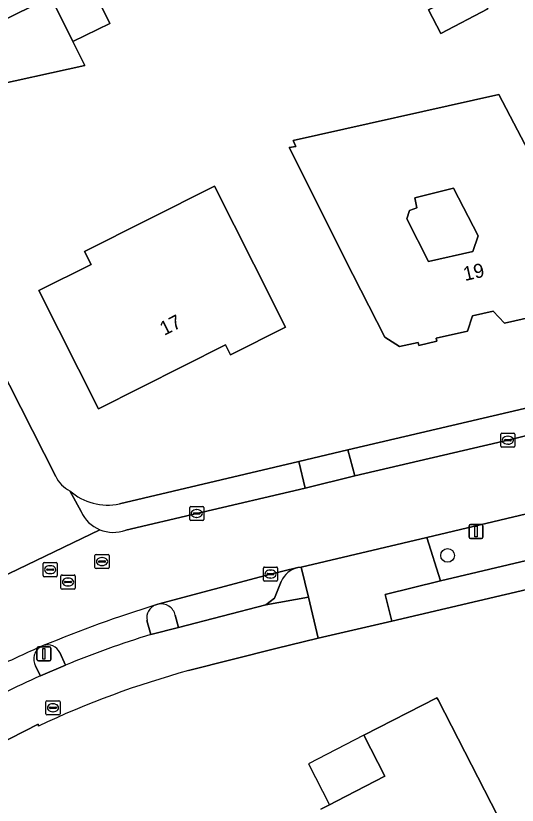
# Model space of a CAD drawing. Extents: x 162722 to 165104, y 384719 to 386284.
# Drawn here: x 163906.4 to 163942.1, y 384936 to 384992.1 of the extents above; entities that cross this region are included whole.
import ezdxf

# ---------------------------------------------------------------- set-up
doc = ezdxf.new("R2010")
doc.units = 0
for name, color, linetype in [('IMGEO_Boom', 7, 'Continuous'), ('IMGEO_Brandkraan', 7, 'Continuous'), ('IMGEO_Erf', 7, 'Continuous'), ('IMGEO_Groenvoorziening', 7, 'Continuous'), ('IMGEO_Kolk', 7, 'Continuous'), ('IMGEO_Lichtmast', 7, 'Continuous'), ('IMGEO_Pand', 7, 'Continuous'), ('IMGEO_Pand_nummerreeks', 7, 'Continuous'), ('IMGEO_Pand_overbouw', 7, 'Continuous'), ('IMGEO_Parkeervlak_open', 7, 'Continuous'), ('IMGEO_Rijbaan_lokaal_open', 7, 'Continuous'), ('IMGEO_Rioolput', 7, 'Continuous'), ('IMGEO_Voetpad_open', 7, 'Continuous')]:
    doc.layers.add(name, color=color, linetype=linetype)

msp = doc.modelspace()

# ---------------------------------------------------------------- linework, layer by layer
at = {"layer": 'IMGEO_Boom'}
msp.add_circle((163937.119, 384953.735), 0.489, dxfattribs=at)
at = {"layer": 'IMGEO_Brandkraan'}
for p, q in [((163908.59, 384942.495), (163908.59, 384943.347)), ((163908.665, 384943.421), (163909.517, 384943.421)), ((163908.849, 384942.915), (163908.849, 384942.927)), ((163908.892, 384942.964), (163909.29, 384942.964)), ((163909.078, 384943.201), (163909.103, 384943.201)), ((163909.333, 384942.927), (163909.333, 384942.915)), ((163909.591, 384943.347), (163909.591, 384942.495)), ((163909.517, 384942.421), (163908.665, 384942.421)), ((163909.287, 384942.878), (163908.889, 384942.878)), ((163909.101, 384942.641), (163909.076, 384942.641))]:
    msp.add_line(p, q, dxfattribs=at)
for points in [[(163908.59, 384942.495), (163908.59, 384943.347)], [(163908.665, 384943.421), (163909.517, 384943.421)], [(163909.591, 384943.347), (163909.591, 384942.495)], [(163909.517, 384942.421), (163908.665, 384942.421)]]:
    msp.add_lwpolyline(points, dxfattribs=at)
for centre, radius, start, end in [((163908.667, 384943.345), 0.0765, 91.552, 178.448), ((163908.667, 384943.345), 0.0765, 91.552, 178.448), ((163908.889, 384942.924), 0.0403, 85.8775, 175.7526), ((163908.886, 384942.914), 0.0366, 178.938, 274.7102), ((163909.29, 384942.921), 0.043, 264.8664, 352.4533), ((163909.294, 384942.926), 0.0386, 1.7309, 96.639), ((163909.515, 384943.345), 0.0765, 1.552, 88.448), ((163909.515, 384943.345), 0.0765, 1.552, 88.448), ((163908.667, 384942.497), 0.0765, 181.552, 268.448), ((163908.667, 384942.497), 0.0765, 181.552, 268.448), ((163909.515, 384942.497), 0.0765, 271.552, 358.448), ((163909.515, 384942.497), 0.0765, 271.552, 358.448)]:
    msp.add_arc(centre, radius, start, end, dxfattribs=at)
for centre, major_axis, ratio, start_param, end_param in [((163909.077, 384942.921), (-0.387, 0.002), 0.722429, 4.712389, 7.853982), ((163909.102, 384942.921), (-0.39, 0.002), 0.717154, 1.570796, 4.712389)]:
    msp.add_ellipse(centre, major_axis=major_axis, ratio=ratio, start_param=start_param, end_param=end_param, dxfattribs=at)
at = {"layer": 'IMGEO_Erf'}
for points in [[(163882.032, 385013.018), (163888.642, 385000), (163909.281, 384959.35)], [(163913.816, 384957.404), (163926.539, 384960.407), (163930.036, 384961.223), (163943.693, 384964.44), (163948.458, 384965.545), (163956.397, 384967.448), (163961.373, 384968.617), (163971.306, 384970.962)], [(163975.92, 384959.258), (163968.134, 384957.317), (163963.115, 384956.107), (163933.164, 384949.08), (163927.927, 384947.854), (163924.926, 384947.138), (163918.721, 384945.558)], [(163928.112, 384935.718), (163928.727, 384936.034), (163929.219, 384936.287), (163932.661, 384938.054), (163931.165, 384940.968), (163936.357, 384943.634), (163936.439, 384943.474), (163941.619, 384933.387)], [(163908.065, 384941.624), (163908.032, 384941.753), (163901.088, 384938.216)]]:
    msp.add_lwpolyline(points, dxfattribs=at)
for points in [[(163911.349, 384988.529), (163904.023, 384986.91), (163902.431, 384990.1), (163902.388, 384990.186), (163908.918, 384993.403), (163909.148, 384992.941), (163911.782, 384994.239), (163913.125, 384991.512), (163910.505, 384990.221)], [(163935.761, 384992.482), (163939.091, 384994.231), (163939.975, 384992.549), (163936.645, 384990.8)], [(163940.76, 384986.466), (163945.807, 384976.829), (163948.127, 384972.399), (163947.687, 384972.29), (163947.865, 384971.742), (163941.151, 384970.237), (163940.349, 384971.083), (163938.885, 384970.754), (163938.527, 384969.649), (163936.314, 384969.153), (163936.363, 384968.939), (163935.075, 384968.65), (163935.026, 384968.863), (163933.698, 384968.566), (163932.657, 384969.226), (163930.383, 384973.68), (163925.858, 384982.688), (163926.334, 384982.782), (163926.145, 384983.19)], [(163915.805, 384977.558), (163920.563, 384979.952), (163923.347, 384974.42), (163925.595, 384969.953), (163921.691, 384967.989), (163921.339, 384968.688), (163912.311, 384964.145), (163908.088, 384972.536), (163911.796, 384974.401), (163911.338, 384975.31)], [(163934.778, 384979.126), (163934.942, 384978.416), (163934.419, 384978.233), (163934.211, 384977.636), (163935.758, 384974.607), (163938.9, 384975.313), (163939.291, 384976.438), (163937.528, 384979.804)]]:
    msp.add_lwpolyline(points, close=True, dxfattribs=at)
for centre, radius, start, end in [((163911.238, 384960.278), 2.166, 205.3701, 244.008), ((163912.954, 384961.299), 3.989, 228.0763, 282.4718), ((163936.044, 384882.237), 65.648, 105.30008, 115.22637)]:
    msp.add_arc(centre, radius, start, end, dxfattribs=at)
at = {"layer": 'IMGEO_Groenvoorziening'}
msp.add_lwpolyline([(163936.605, 384951.924), (163962.352, 384958.013), (163960.784, 384960.984), (163958.798, 384960.498), (163942.724, 384956.689), (163935.642, 384955.001)], close=True, dxfattribs=at)
at = {"layer": 'IMGEO_Kolk'}
for p, q in [((163940.895, 384961.491), (163940.895, 384962.343)), ((163940.97, 384962.417), (163941.822, 384962.417)), ((163941.197, 384961.96), (163941.595, 384961.96)), ((163941.383, 384962.197), (163941.408, 384962.197)), ((163941.896, 384962.343), (163941.896, 384961.491)), ((163941.822, 384961.417), (163940.97, 384961.417)), ((163941.154, 384961.911), (163941.154, 384961.923)), ((163941.592, 384961.874), (163941.194, 384961.874)), ((163941.406, 384961.637), (163941.381, 384961.637)), ((163941.638, 384961.923), (163941.638, 384961.911)), ((163918.799, 384956.286), (163918.799, 384957.138)), ((163918.874, 384957.212), (163919.726, 384957.212)), ((163919.287, 384956.992), (163919.312, 384956.992)), ((163919.8, 384957.138), (163919.8, 384956.286)), ((163919.058, 384956.706), (163919.058, 384956.718)), ((163919.496, 384956.669), (163919.098, 384956.669)), ((163919.101, 384956.755), (163919.499, 384956.755)), ((163919.31, 384956.432), (163919.285, 384956.432)), ((163919.542, 384956.718), (163919.542, 384956.706)), ((163919.726, 384956.212), (163918.874, 384956.212)), ((163924.039, 384951.987), (163924.039, 384952.839)), ((163924.114, 384952.913), (163924.966, 384952.913)), ((163924.341, 384952.456), (163924.739, 384952.456)), ((163924.527, 384952.693), (163924.552, 384952.693)), ((163925.04, 384952.839), (163925.04, 384951.987)), ((163924.966, 384951.913), (163924.114, 384951.913)), ((163924.298, 384952.407), (163924.298, 384952.419)), ((163924.736, 384952.37), (163924.338, 384952.37)), ((163924.55, 384952.133), (163924.525, 384952.133)), ((163924.782, 384952.419), (163924.782, 384952.407))]:
    msp.add_line(p, q, dxfattribs=at)
for points in [[(163940.895, 384961.491), (163940.895, 384962.343)], [(163940.97, 384962.417), (163941.822, 384962.417)], [(163941.896, 384962.343), (163941.896, 384961.491)], [(163941.822, 384961.417), (163940.97, 384961.417)], [(163918.799, 384956.286), (163918.799, 384957.138)], [(163918.874, 384957.212), (163919.726, 384957.212)], [(163919.8, 384957.138), (163919.8, 384956.286)], [(163919.726, 384956.212), (163918.874, 384956.212)], [(163924.039, 384951.987), (163924.039, 384952.839)], [(163924.114, 384952.913), (163924.966, 384952.913)], [(163925.04, 384952.839), (163925.04, 384951.987)], [(163924.966, 384951.913), (163924.114, 384951.913)]]:
    msp.add_lwpolyline(points, dxfattribs=at)
for centre, radius, start, end in [((163940.972, 384962.341), 0.0765, 91.552, 178.448), ((163940.972, 384962.341), 0.0765, 91.552, 178.448), ((163941.194, 384961.92), 0.0403, 85.8775, 175.7526), ((163941.599, 384961.922), 0.0386, 1.7309, 96.639), ((163941.82, 384962.341), 0.0765, 1.552, 88.448), ((163941.82, 384962.341), 0.0765, 1.552, 88.448), ((163940.972, 384961.493), 0.0765, 181.552, 268.448), ((163940.972, 384961.493), 0.0765, 181.552, 268.448), ((163941.191, 384961.91), 0.0366, 178.938, 274.7102), ((163941.595, 384961.917), 0.043, 264.8664, 352.4533), ((163941.82, 384961.493), 0.0765, 271.552, 358.448), ((163941.82, 384961.493), 0.0765, 271.552, 358.448), ((163918.876, 384957.136), 0.0765, 91.552, 178.448), ((163918.876, 384957.136), 0.0765, 91.552, 178.448), ((163919.724, 384957.136), 0.0765, 1.552, 88.448), ((163919.724, 384957.136), 0.0765, 1.552, 88.448), ((163919.098, 384956.715), 0.0403, 85.8775, 175.7526), ((163919.095, 384956.705), 0.0366, 178.938, 274.7102), ((163919.499, 384956.712), 0.043, 264.8664, 352.4533), ((163919.503, 384956.717), 0.0386, 1.7309, 96.639), ((163918.876, 384956.288), 0.0765, 181.552, 268.448), ((163918.876, 384956.288), 0.0765, 181.552, 268.448), ((163919.724, 384956.288), 0.0765, 271.552, 358.448), ((163919.724, 384956.288), 0.0765, 271.552, 358.448), ((163924.116, 384952.837), 0.0765, 91.552, 178.448), ((163924.116, 384952.837), 0.0765, 91.552, 178.448), ((163924.338, 384952.416), 0.0403, 85.8775, 175.7526), ((163924.743, 384952.418), 0.0386, 1.7309, 96.639), ((163924.964, 384952.837), 0.0765, 1.552, 88.448), ((163924.964, 384952.837), 0.0765, 1.552, 88.448), ((163924.116, 384951.989), 0.0765, 181.552, 268.448), ((163924.116, 384951.989), 0.0765, 181.552, 268.448), ((163924.335, 384952.406), 0.0366, 178.938, 274.7102), ((163924.739, 384952.413), 0.043, 264.8664, 352.4533), ((163924.964, 384951.989), 0.0765, 271.552, 358.448), ((163924.964, 384951.989), 0.0765, 271.552, 358.448)]:
    msp.add_arc(centre, radius, start, end, dxfattribs=at)
for centre, major_axis, ratio, start_param, end_param in [((163941.382, 384961.917), (-0.387, 0.002), 0.722429, 4.712389, 7.853982), ((163941.407, 384961.917), (-0.39, 0.002), 0.717154, 1.570796, 4.712389), ((163919.286, 384956.712), (-0.387, 0.002), 0.722429, 4.712389, 7.853982), ((163919.311, 384956.712), (-0.39, 0.002), 0.717154, 1.570796, 4.712389), ((163924.526, 384952.413), (-0.387, 0.002), 0.722429, 4.712389, 7.853982), ((163924.551, 384952.413), (-0.39, 0.002), 0.717154, 1.570796, 4.712389)]:
    msp.add_ellipse(centre, major_axis=major_axis, ratio=ratio, start_param=start_param, end_param=end_param, dxfattribs=at)
at = {"layer": 'IMGEO_Lichtmast'}
for p, q in [((163938.638, 384955.043), (163938.638, 384955.843)), ((163938.638, 384955.843), (163938.638, 384955.043)), ((163938.738, 384955.943), (163939.528, 384955.943)), ((163939.528, 384955.943), (163938.738, 384955.943)), ((163939.628, 384955.843), (163939.628, 384955.043)), ((163939.628, 384955.043), (163939.628, 384955.843)), ((163939.528, 384954.943), (163938.738, 384954.943)), ((163938.738, 384954.943), (163939.528, 384954.943)), ((163907.95, 384946.353), (163907.95, 384947.153)), ((163907.95, 384947.153), (163907.95, 384946.353)), ((163908.05, 384947.253), (163908.84, 384947.253)), ((163908.84, 384947.253), (163908.05, 384947.253)), ((163908.94, 384947.153), (163908.94, 384946.353)), ((163908.94, 384946.353), (163908.94, 384947.153)), ((163908.84, 384946.253), (163908.05, 384946.253)), ((163908.05, 384946.253), (163908.84, 384946.253))]:
    msp.add_line(p, q, dxfattribs=at)
for points in [[(163939.058, 384955.818), (163939.208, 384955.818), (163939.208, 384955.068), (163939.058, 384955.068), (163939.058, 384955.818)], [(163908.37, 384947.128), (163908.52, 384947.128), (163908.52, 384946.378), (163908.37, 384946.378), (163908.37, 384947.128)]]:
    msp.add_lwpolyline(points, dxfattribs=at)
for centre, start, end in [((163938.738, 384955.843), 90, 180), ((163938.738, 384955.843), 90, 180), ((163939.528, 384955.843), 0, 90), ((163939.528, 384955.843), 360, 90), ((163938.738, 384955.043), 180, 270), ((163938.738, 384955.043), 180, 270), ((163939.528, 384955.043), 270, 0), ((163939.528, 384955.043), 270, 0), ((163908.05, 384947.153), 90, 180), ((163908.05, 384947.153), 90, 180), ((163908.84, 384947.153), 0, 90), ((163908.84, 384947.153), 360, 90), ((163908.05, 384946.353), 180, 270), ((163908.05, 384946.353), 180, 270), ((163908.84, 384946.353), 270, 0), ((163908.84, 384946.353), 270, 0)]:
    msp.add_arc(centre, 0.1, start, end, dxfattribs=at)
at = {"layer": 'IMGEO_Pand'}
for points in [[(163911.782, 384994.239), (163909.148, 384992.941), (163910.505, 384990.221), (163913.125, 384991.512)], [(163935.761, 384992.482), (163936.645, 384990.8), (163939.975, 384992.549), (163939.091, 384994.231)], [(163910.505, 384990.221), (163909.148, 384992.941), (163908.918, 384993.403), (163902.388, 384990.186), (163902.431, 384990.1), (163904.023, 384986.91), (163911.349, 384988.529)], [(163945.807, 384976.829), (163940.76, 384986.466), (163926.145, 384983.19), (163926.334, 384982.782), (163925.858, 384982.688), (163930.383, 384973.68), (163932.657, 384969.226), (163933.698, 384968.566), (163935.026, 384968.863), (163935.075, 384968.65), (163936.363, 384968.939), (163936.314, 384969.153), (163938.527, 384969.649), (163938.885, 384970.754), (163940.349, 384971.083), (163941.151, 384970.237), (163947.865, 384971.742), (163947.687, 384972.29), (163948.127, 384972.399)], [(163911.338, 384975.31), (163911.796, 384974.401), (163908.088, 384972.536), (163912.311, 384964.145), (163921.339, 384968.688), (163921.691, 384967.989), (163925.595, 384969.953), (163923.347, 384974.42), (163920.563, 384979.952), (163915.805, 384977.558)], [(163934.778, 384979.126), (163937.528, 384979.804), (163939.291, 384976.438), (163938.9, 384975.313), (163935.758, 384974.607), (163934.211, 384977.636), (163934.419, 384978.233), (163934.942, 384978.416)]]:
    msp.add_lwpolyline(points, close=True, dxfattribs=at)
msp.add_lwpolyline([(163941.619, 384933.387), (163936.439, 384943.474), (163936.357, 384943.634), (163931.165, 384940.968), (163932.661, 384938.054), (163929.219, 384936.287), (163928.727, 384936.034), (163928.112, 384935.718)], dxfattribs=at)
at = {"layer": 'IMGEO_Pand_overbouw'}
msp.add_lwpolyline([(163931.165, 384940.968), (163927.231, 384938.948), (163928.727, 384936.034), (163929.219, 384936.287), (163932.661, 384938.054)], close=True, dxfattribs=at)
at = {"layer": 'IMGEO_Parkeervlak_open'}
msp.add_lwpolyline([(163930.539, 384959.379), (163941.396, 384961.917), (163944.127, 384962.571), (163943.693, 384964.44), (163930.036, 384961.223)], close=True, dxfattribs=at)
for points in [[(163927.004, 384958.519), (163926.539, 384960.407), (163913.816, 384957.404)], [(163910.289, 384958.331), (163911.083, 384956.847)], [(163914.255, 384955.535), (163919.3, 384956.712), (163927.004, 384958.519)], [(163926.475, 384952.875), (163924.54, 384952.413), (163916.547, 384950.264)], [(163917.774, 384949.488), (163917.994, 384948.624), (163924.21, 384950.228), (163924.811, 384950.701), (163925.3, 384951.892)], [(163916.036, 384948.113), (163915.767, 384949.11)], [(163909.587, 384946.845), (163909.973, 384945.94)], [(163908.212, 384945.196), (163907.86, 384945.88)]]:
    msp.add_lwpolyline(points, dxfattribs=at)
for centre, radius, start, end in [((163912.954, 384961.299), 3.989, 228.0763, 282.4718), ((163913.366, 384957.876), 2.504, 204.261, 247.5382), ((163913.366, 384957.874), 2.502, 247.51, 290.8141), ((163926.933, 384951.134), 1.8, 104.7294, 155.102), ((163943.69, 384862.283), 92.077, 107.23823, 112.53587), ((163916.731, 384949.298), 0.982, 109.5177, 191.0368), ((163916.776, 384949.268), 1.022, 12.4188, 102.9596), ((163933.705, 384889.269), 61.439, 106.71334, 112.72237), ((163908.708, 384946.388), 0.991, 27.5021, 108.1315), ((163938.782, 384877.001), 76.612, 113.47653, 116.01721), ((163908.708, 384946.389), 0.989, 116.822, 210.9613), ((163938.457, 384877.857), 73.819, 114.18669, 118.76979)]:
    msp.add_arc(centre, radius, start, end, dxfattribs=at)
at = {"layer": 'IMGEO_Rijbaan_lokaal_open'}
for points in [[(163909.281, 384959.35), (163888.642, 385000), (163882.032, 385013.018)], [(163971.757, 384969.098), (163970.189, 384968.716), (163961.803, 384966.736), (163957.131, 384965.627), (163956.845, 384965.547), (163948.878, 384963.68), (163944.127, 384962.571), (163941.396, 384961.917), (163930.539, 384959.379), (163927.004, 384958.519), (163919.3, 384956.712), (163914.255, 384955.535)], [(163935.642, 384955.001), (163942.724, 384956.689), (163958.798, 384960.498), (163960.784, 384960.984), (163965.641, 384962.088), (163972.665, 384963.778)], [(163911.083, 384956.847), (163910.289, 384958.331)], [(163912.409, 384955.562), (163902.719, 384950.896), (163905.177, 384945.85)], [(163902.719, 384950.896), (163912.409, 384955.562)], [(163916.403, 384950.224), (163916.547, 384950.264), (163924.54, 384952.413), (163926.475, 384952.875), (163926.707, 384952.909), (163935.642, 384955.001)], [(163908.262, 384947.272), (163908.4, 384947.329)]]:
    msp.add_lwpolyline(points, dxfattribs=at)
for centre, radius, start, end in [((163911.238, 384960.278), 2.166, 205.3701, 244.008), ((163913.366, 384957.876), 2.504, 204.261, 247.5382), ((163913.366, 384957.874), 2.502, 247.51, 290.8141), ((163943.69, 384862.283), 92.077, 107.23823, 112.53587), ((163938.782, 384877.001), 76.612, 113.47653, 116.01721)]:
    msp.add_arc(centre, radius, start, end, dxfattribs=at)
at = {"layer": 'IMGEO_Rioolput'}
for p, q in [((163912.072, 384952.874), (163912.072, 384953.726)), ((163912.147, 384953.8), (163912.999, 384953.8)), ((163912.56, 384953.58), (163912.585, 384953.58)), ((163913.073, 384953.726), (163913.073, 384952.874)), ((163908.388, 384952.301), (163908.388, 384953.153)), ((163908.463, 384953.227), (163909.315, 384953.227)), ((163908.876, 384953.007), (163908.901, 384953.007)), ((163909.389, 384953.153), (163909.389, 384952.301)), ((163912.331, 384953.294), (163912.331, 384953.306)), ((163912.769, 384953.257), (163912.371, 384953.257)), ((163912.374, 384953.343), (163912.772, 384953.343)), ((163912.583, 384953.02), (163912.558, 384953.02)), ((163912.815, 384953.306), (163912.815, 384953.294)), ((163908.647, 384952.721), (163908.647, 384952.733)), ((163909.085, 384952.684), (163908.687, 384952.684)), ((163908.69, 384952.77), (163909.088, 384952.77)), ((163908.899, 384952.447), (163908.874, 384952.447)), ((163909.131, 384952.733), (163909.131, 384952.721)), ((163912.999, 384952.8), (163912.147, 384952.8)), ((163909.315, 384952.227), (163908.463, 384952.227)), ((163909.657, 384951.42), (163909.657, 384952.272)), ((163909.732, 384952.346), (163910.584, 384952.346)), ((163909.959, 384951.889), (163910.357, 384951.889)), ((163910.145, 384952.126), (163910.17, 384952.126)), ((163910.658, 384952.272), (163910.658, 384951.42)), ((163910.584, 384951.346), (163909.732, 384951.346)), ((163909.916, 384951.84), (163909.916, 384951.852)), ((163910.354, 384951.803), (163909.956, 384951.803)), ((163910.168, 384951.566), (163910.143, 384951.566)), ((163910.4, 384951.852), (163910.4, 384951.84))]:
    msp.add_line(p, q, dxfattribs=at)
for points in [[(163912.072, 384952.874), (163912.072, 384953.726)], [(163912.147, 384953.8), (163912.999, 384953.8)], [(163913.073, 384953.726), (163913.073, 384952.874)], [(163908.388, 384952.301), (163908.388, 384953.153)], [(163908.463, 384953.227), (163909.315, 384953.227)], [(163909.389, 384953.153), (163909.389, 384952.301)], [(163912.999, 384952.8), (163912.147, 384952.8)], [(163909.315, 384952.227), (163908.463, 384952.227)], [(163909.657, 384951.42), (163909.657, 384952.272)], [(163909.732, 384952.346), (163910.584, 384952.346)], [(163910.658, 384952.272), (163910.658, 384951.42)], [(163910.584, 384951.346), (163909.732, 384951.346)]]:
    msp.add_lwpolyline(points, dxfattribs=at)
for centre, radius, start, end in [((163912.149, 384953.724), 0.0765, 91.552, 178.448), ((163912.149, 384953.724), 0.0765, 91.552, 178.448), ((163912.997, 384953.724), 0.0765, 1.552, 88.448), ((163912.997, 384953.724), 0.0765, 1.552, 88.448), ((163908.465, 384953.151), 0.0765, 91.552, 178.448), ((163908.465, 384953.151), 0.0765, 91.552, 178.448), ((163909.313, 384953.151), 0.0765, 1.552, 88.448), ((163909.313, 384953.151), 0.0765, 1.552, 88.448), ((163912.371, 384953.303), 0.0403, 85.8775, 175.7526), ((163912.368, 384953.293), 0.0366, 178.938, 274.7102), ((163912.772, 384953.3), 0.043, 264.8664, 352.4533), ((163912.776, 384953.305), 0.0386, 1.7309, 96.639), ((163908.687, 384952.73), 0.0403, 85.8775, 175.7526), ((163908.684, 384952.72), 0.0366, 178.938, 274.7102), ((163909.088, 384952.727), 0.043, 264.8664, 352.4533), ((163909.092, 384952.732), 0.0386, 1.7309, 96.639), ((163912.149, 384952.876), 0.0765, 181.552, 268.448), ((163912.149, 384952.876), 0.0765, 181.552, 268.448), ((163912.997, 384952.876), 0.0765, 271.552, 358.448), ((163912.997, 384952.876), 0.0765, 271.552, 358.448), ((163908.465, 384952.303), 0.0765, 181.552, 268.448), ((163908.465, 384952.303), 0.0765, 181.552, 268.448), ((163909.313, 384952.303), 0.0765, 271.552, 358.448), ((163909.313, 384952.303), 0.0765, 271.552, 358.448), ((163909.734, 384952.27), 0.0765, 91.552, 178.448), ((163909.734, 384952.27), 0.0765, 91.552, 178.448), ((163909.956, 384951.849), 0.0403, 85.8775, 175.7526), ((163910.361, 384951.851), 0.0386, 1.7309, 96.639), ((163910.582, 384952.27), 0.0765, 1.552, 88.448), ((163910.582, 384952.27), 0.0765, 1.552, 88.448), ((163909.734, 384951.422), 0.0765, 181.552, 268.448), ((163909.734, 384951.422), 0.0765, 181.552, 268.448), ((163909.953, 384951.839), 0.0366, 178.938, 274.7102), ((163910.357, 384951.846), 0.043, 264.8664, 352.4533), ((163910.582, 384951.422), 0.0765, 271.552, 358.448), ((163910.582, 384951.422), 0.0765, 271.552, 358.448)]:
    msp.add_arc(centre, radius, start, end, dxfattribs=at)
for centre, major_axis, ratio, start_param, end_param in [((163912.559, 384953.3), (-0.387, 0.002), 0.722429, 4.712389, 7.853982), ((163912.584, 384953.3), (-0.39, 0.002), 0.717154, 1.570796, 4.712389), ((163908.875, 384952.727), (-0.387, 0.002), 0.722429, 4.712389, 7.853982), ((163908.9, 384952.727), (-0.39, 0.002), 0.717154, 1.570796, 4.712389), ((163910.144, 384951.846), (-0.387, 0.002), 0.722429, 4.712389, 7.853982), ((163910.169, 384951.846), (-0.39, 0.002), 0.717154, 1.570796, 4.712389)]:
    msp.add_ellipse(centre, major_axis=major_axis, ratio=ratio, start_param=start_param, end_param=end_param, dxfattribs=at)
at = {"layer": 'IMGEO_Voetpad_open'}
for points in [[(163930.539, 384959.379), (163930.036, 384961.223), (163926.539, 384960.407), (163927.004, 384958.519)], [(163936.605, 384951.924), (163932.682, 384950.96), (163933.164, 384949.08), (163963.115, 384956.107), (163962.352, 384958.013)], [(163935.642, 384955.001), (163926.707, 384952.909), (163927.234, 384950.768), (163927.927, 384947.854), (163933.164, 384949.08), (163932.682, 384950.96), (163936.605, 384951.924)]]:
    msp.add_lwpolyline(points, close=True, dxfattribs=at)
for points in [[(163925.3, 384951.892), (163924.811, 384950.701), (163924.21, 384950.228), (163927.234, 384950.768), (163926.707, 384952.909), (163926.475, 384952.875)], [(163918.721, 384945.558), (163924.926, 384947.138), (163927.927, 384947.854), (163927.234, 384950.768), (163924.21, 384950.228), (163917.994, 384948.624), (163916.036, 384948.113)], [(163916.547, 384950.264), (163916.403, 384950.224)], [(163915.767, 384949.11), (163916.036, 384948.113), (163917.994, 384948.624), (163917.774, 384949.488)], [(163907.86, 384945.88), (163908.212, 384945.196), (163909.973, 384945.94), (163909.587, 384946.845)], [(163908.4, 384947.329), (163908.262, 384947.272)], [(163909.973, 384945.94), (163908.212, 384945.196)], [(163902.928, 384942.564), (163899.79, 384940.765), (163901.088, 384938.216), (163908.032, 384941.753), (163908.065, 384941.624)]]:
    msp.add_lwpolyline(points, dxfattribs=at)
for centre, radius, start, end in [((163926.933, 384951.134), 1.8, 104.7294, 155.102), ((163916.731, 384949.298), 0.982, 109.5177, 191.0368), ((163916.776, 384949.268), 1.022, 12.4188, 102.9596), ((163933.705, 384889.269), 61.439, 106.71334, 112.72237), ((163908.708, 384946.388), 0.991, 27.5021, 108.1315), ((163908.708, 384946.389), 0.989, 116.822, 210.9613), ((163938.457, 384877.857), 73.819, 114.18669, 118.76979), ((163936.044, 384882.237), 65.648, 105.30008, 115.22637)]:
    msp.add_arc(centre, radius, start, end, dxfattribs=at)

# ---------------------------------------------------------------- texts
at = {"layer": 'IMGEO_Pand_nummerreeks'}
for s, rotation, p in [('19', 12.6681, (163938.347, 384973.215)), ('17', 26.7121, (163916.987, 384969.319))]:
    msp.add_text(s, height=1, rotation=rotation, dxfattribs=at).set_placement(p)

doc.saveas('drawing.dxf')
